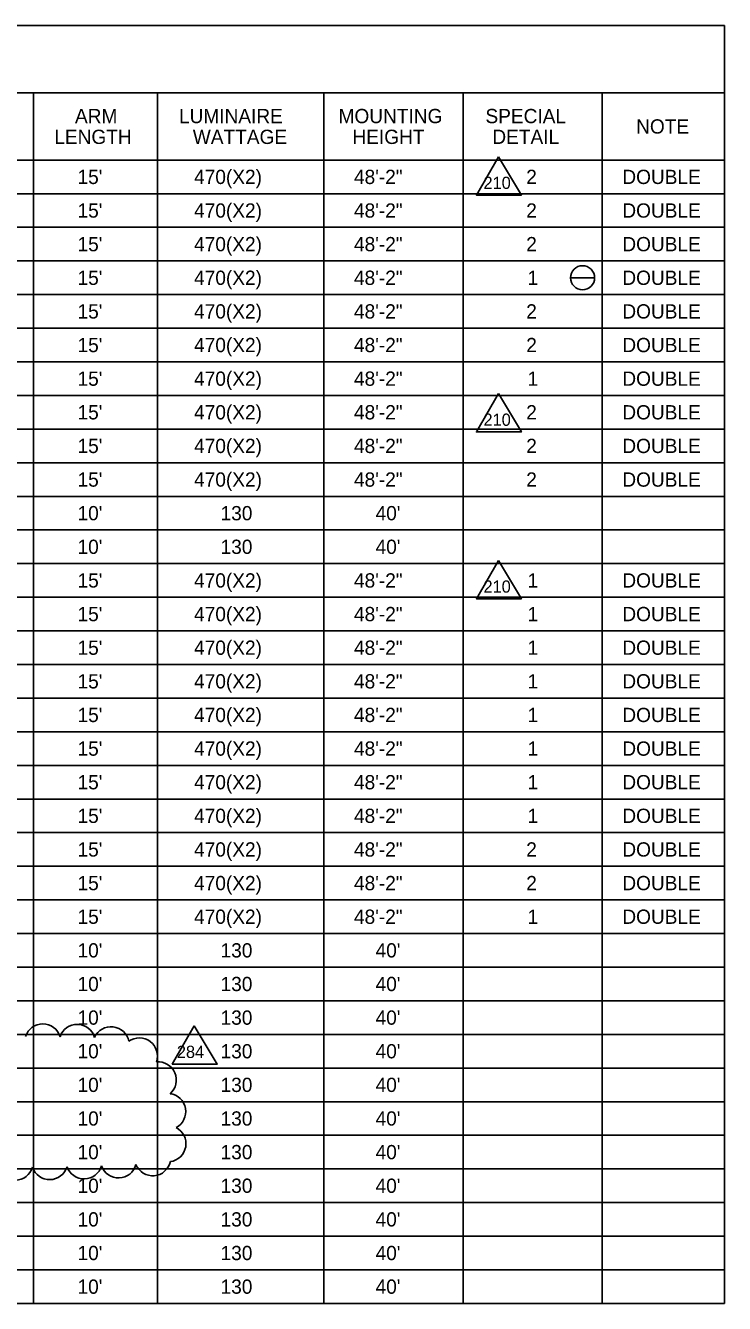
# Model space of a CAD drawing. Extents: x -816.7 to -800.7, y -2197.9 to -2187.9.
# Drawn here: x -812.04 to -808.61, y -2194.13 to -2187.86 of the extents above; entities that cross this region are included whole.
import ezdxf

# ---------------------------------------------------------------- set-up
doc = ezdxf.new("R2010")
doc.units = 0
for name, color, linetype in [('Cloud_dp', 7, 'Continuous'), ('SumBoxBorder_dp', 7, 'Continuous'), ('SumBoxLines_dp', 7, 'Continuous'), ('SumBoxLinesMin_dp', 7, 'Continuous'), ('TextLabel', 7, 'Continuous')]:
    doc.layers.add(name, color=color, linetype=linetype)

msp = doc.modelspace()

# ---------------------------------------------------------------- linework, layer by layer
at = {"layer": 'Cloud_dp'}
for points in [[(-809.7225, -2188.4998), (-809.8303, -2188.6879), (-809.6096, -2188.6879)], [(-809.7225, -2189.6621), (-809.8303, -2189.8502), (-809.6096, -2189.8502)], [(-809.7225, -2190.4807), (-809.8303, -2190.6688), (-809.6096, -2190.6688)], [(-811.215, -2192.7638), (-811.3227, -2192.9519), (-811.1021, -2192.9519)]]:
    msp.add_lwpolyline(points, close=True, dxfattribs=at)
for centre, radius, start, end in [((-811.9584, -2192.8432), 0.0887, 16.98047, 161.98047), ((-811.7894, -2192.8456), 0.0887, 16.37548, 161.37548), ((-811.6233, -2192.8569), 0.0887, 10.88611, 155.88611), ((-811.4843, -2192.9121), 0.0887, 340.74412, 125.74412), ((-811.3917, -2193.0297), 0.0887, 310.70221, 95.70221), ((-811.3452, -2193.185), 0.0887, 297.61139, 82.61139), ((-811.3444, -2193.3426), 0.0887, 277.92335, 62.92335), ((-811.4189, -2193.4112), 0.0888, 202.48791, 347.48791), ((-812.0936, -2193.4325), 0.0887, 198.24258, 343.24258), ((-811.9244, -2193.43), 0.0887, 198.48321, 343.48321), ((-811.7554, -2193.4265), 0.0887, 198.85675, 343.85675), ((-811.5865, -2193.4215), 0.0887, 199.56532, 344.56532)]:
    msp.add_arc(centre, radius, start, end, dxfattribs=at)
at = {"layer": 'SumBoxBorder_dp'}
for p, q in [((-816.0386, -2187.8562), (-808.6136, -2187.8562)), ((-808.6136, -2187.8562), (-808.6136, -2194.1262)), ((-808.6136, -2187.8562), (-808.6136, -2194.1262)), ((-816.0386, -2188.1862), (-808.6136, -2188.1862)), ((-816.0386, -2188.1862), (-808.6136, -2188.1862)), ((-816.0386, -2194.1262), (-808.6136, -2194.1262))]:
    msp.add_line(p, q, dxfattribs=at)
at = {"layer": 'SumBoxLines_dp'}
for p, q in [((-812.0036, -2188.1862), (-812.0036, -2194.1262)), ((-812.0036, -2188.1862), (-812.0036, -2194.1262)), ((-811.3961, -2188.1862), (-811.3961, -2194.1262)), ((-811.3961, -2188.1862), (-811.3961, -2194.1262)), ((-810.5786, -2188.1862), (-810.5786, -2194.1262)), ((-810.5786, -2188.1862), (-810.5786, -2194.1262)), ((-809.8961, -2188.1862), (-809.8961, -2194.1262)), ((-809.8961, -2188.1862), (-809.8961, -2192.3112)), ((-809.2136, -2188.1862), (-809.2136, -2194.1262)), ((-816.0386, -2188.5162), (-808.6136, -2188.5162)), ((-809.8961, -2192.4762), (-809.8961, -2194.1262))]:
    msp.add_line(p, q, dxfattribs=at)
at = {"layer": 'SumBoxLinesMin_dp'}
for p, q in [((-816.0386, -2188.5162), (-808.6136, -2188.5162)), ((-816.0386, -2188.6812), (-808.6136, -2188.6812)), ((-816.0386, -2188.6812), (-808.6136, -2188.6812)), ((-816.0386, -2188.8462), (-808.6136, -2188.8462)), ((-816.0386, -2188.8462), (-808.6136, -2188.8462)), ((-816.0386, -2189.0112), (-808.6136, -2189.0112)), ((-816.0386, -2189.0112), (-808.6136, -2189.0112)), ((-816.0386, -2189.1762), (-808.6136, -2189.1762)), ((-816.0386, -2189.1762), (-808.6136, -2189.1762)), ((-816.0386, -2189.3412), (-808.6136, -2189.3412)), ((-816.0386, -2189.3412), (-808.6136, -2189.3412)), ((-816.0386, -2189.5062), (-808.6136, -2189.5062)), ((-816.0386, -2189.5062), (-808.6136, -2189.5062)), ((-816.0386, -2189.6712), (-808.6136, -2189.6712)), ((-816.0386, -2189.6712), (-808.6136, -2189.6712)), ((-816.0386, -2189.8362), (-808.6136, -2189.8362)), ((-816.0386, -2189.8362), (-808.6136, -2189.8362)), ((-816.0386, -2190.0012), (-808.6136, -2190.0012)), ((-816.0386, -2190.0012), (-808.6136, -2190.0012)), ((-816.0386, -2190.1662), (-808.6136, -2190.1662)), ((-816.0386, -2190.1662), (-808.6136, -2190.1662)), ((-816.0386, -2190.3312), (-808.6136, -2190.3312)), ((-816.0386, -2190.3312), (-808.6136, -2190.3312)), ((-816.0386, -2190.4962), (-808.6136, -2190.4962)), ((-816.0386, -2190.4962), (-808.6136, -2190.4962)), ((-816.0386, -2190.6612), (-808.6136, -2190.6612)), ((-816.0386, -2190.6612), (-808.6136, -2190.6612)), ((-816.0386, -2190.8262), (-808.6136, -2190.8262)), ((-816.0386, -2190.8262), (-808.6136, -2190.8262)), ((-816.0386, -2190.9912), (-808.6136, -2190.9912)), ((-816.0386, -2190.9912), (-808.6136, -2190.9912)), ((-816.0386, -2191.1562), (-808.6136, -2191.1562)), ((-816.0386, -2191.1562), (-808.6136, -2191.1562)), ((-816.0386, -2191.3212), (-808.6136, -2191.3212)), ((-816.0386, -2191.3212), (-808.6136, -2191.3212)), ((-816.0386, -2191.4862), (-808.6136, -2191.4862)), ((-816.0386, -2191.4862), (-808.6136, -2191.4862)), ((-816.0386, -2191.6512), (-808.6136, -2191.6512)), ((-816.0386, -2191.6512), (-808.6136, -2191.6512)), ((-816.0386, -2191.8162), (-808.6136, -2191.8162)), ((-816.0386, -2191.8162), (-808.6136, -2191.8162)), ((-816.0386, -2191.9812), (-808.6136, -2191.9812)), ((-816.0386, -2191.9812), (-808.6136, -2191.9812)), ((-816.0386, -2192.1462), (-808.6136, -2192.1462)), ((-816.0386, -2192.1462), (-808.6136, -2192.1462)), ((-816.0386, -2192.3112), (-808.6136, -2192.3112)), ((-816.0386, -2192.3112), (-808.6136, -2192.3112)), ((-816.0386, -2192.4762), (-809.8961, -2192.4762)), ((-816.0386, -2192.4762), (-808.6136, -2192.4762)), ((-809.2136, -2192.4762), (-808.6136, -2192.4762)), ((-816.0386, -2192.6412), (-808.6136, -2192.6412)), ((-816.0386, -2192.6412), (-808.6136, -2192.6412)), ((-816.0386, -2192.8062), (-808.6136, -2192.8062)), ((-816.0386, -2192.8062), (-808.6136, -2192.8062)), ((-816.0386, -2192.9712), (-808.6136, -2192.9712)), ((-816.0386, -2192.9712), (-808.6136, -2192.9712)), ((-816.0386, -2193.1362), (-808.6136, -2193.1362)), ((-816.0386, -2193.1362), (-808.6136, -2193.1362)), ((-816.0386, -2193.3012), (-808.6136, -2193.3012)), ((-816.0386, -2193.3012), (-808.6136, -2193.3012)), ((-816.0386, -2193.4662), (-808.6136, -2193.4662)), ((-816.0386, -2193.4662), (-808.6136, -2193.4662)), ((-816.0386, -2193.6312), (-808.6136, -2193.6312)), ((-816.0386, -2193.6312), (-808.6136, -2193.6312)), ((-816.0386, -2193.7962), (-808.6136, -2193.7962)), ((-816.0386, -2193.7962), (-808.6136, -2193.7962)), ((-816.0386, -2193.9612), (-808.6136, -2193.9612)), ((-816.0386, -2193.9612), (-808.6136, -2193.9612))]:
    msp.add_line(p, q, dxfattribs=at)
at = {"layer": 'TextLabel'}
msp.add_line((-809.3691, -2189.0937), (-809.2505, -2189.0937), dxfattribs=at)
msp.add_line((-809.3691, -2189.0937), (-809.2505, -2189.0937), dxfattribs=at)
msp.add_circle((-809.3098, -2189.0937), 0.0593, dxfattribs=at)
msp.add_arc((-809.3098, -2189.0937), 0.0593, 0, 180, dxfattribs=at)

# ---------------------------------------------------------------- texts
at = {"layer": 'Cloud_dp'}
for s, p in [('210', (-809.7958, -2188.6578)), ('210', (-809.7958, -2189.8201)), ('210', (-809.7958, -2190.6387)), ('284', (-811.3004, -2192.9217))]:
    msp.add_text(s, height=0.05998, rotation=0, dxfattribs=at).set_placement(p)
at = {"layer": 'TextLabel'}
for s, p in [('ARM', (-811.8003, -2188.3352)), ('LUMINAIRE', (-811.29, -2188.3352)), ('MOUNTING', (-810.507, -2188.3352)), ('SPECIAL', (-809.7862, -2188.3352)), ('NOTE', (-809.0469, -2188.3862)), ('LENGTH', (-811.9018, -2188.4372)), ('WATTAGE', (-811.2222, -2188.4372)), ('HEIGHT', (-810.4388, -2188.4372)), ('DETAIL', (-809.7524, -2188.4372)), ("15'", (-811.7878, -2188.6337)), ('470(X2)', (-811.2158, -2188.6337)), ('48\'-2"', (-810.4313, -2188.6337)), ('2', (-809.5862, -2188.6337)), ('DOUBLE', (-809.1146, -2188.6337)), ("15'", (-811.7878, -2188.7987)), ('470(X2)', (-811.2158, -2188.7987)), ('48\'-2"', (-810.4313, -2188.7987)), ('2', (-809.5862, -2188.7987)), ('DOUBLE', (-809.1146, -2188.7987)), ("15'", (-811.7878, -2188.9637)), ('470(X2)', (-811.2158, -2188.9637)), ('48\'-2"', (-810.4313, -2188.9637)), ('2', (-809.5862, -2188.9637)), ('DOUBLE', (-809.1146, -2188.9637)), ("15'", (-811.7878, -2189.1287)), ('470(X2)', (-811.2158, -2189.1287)), ('48\'-2"', (-810.4313, -2189.1287)), ('1', (-809.5795, -2189.1287)), ('DOUBLE', (-809.1146, -2189.1287)), ("15'", (-811.7878, -2189.2937)), ('470(X2)', (-811.2158, -2189.2937)), ('48\'-2"', (-810.4313, -2189.2937)), ('2', (-809.5862, -2189.2937)), ('DOUBLE', (-809.1146, -2189.2937)), ("15'", (-811.7878, -2189.4587)), ('470(X2)', (-811.2158, -2189.4587)), ('48\'-2"', (-810.4313, -2189.4587)), ('2', (-809.5862, -2189.4587)), ('DOUBLE', (-809.1146, -2189.4587)), ("15'", (-811.7878, -2189.6237)), ('470(X2)', (-811.2158, -2189.6237)), ('48\'-2"', (-810.4313, -2189.6237)), ('1', (-809.5795, -2189.6237)), ('DOUBLE', (-809.1146, -2189.6237)), ("15'", (-811.7878, -2189.7887)), ('470(X2)', (-811.2158, -2189.7887)), ('48\'-2"', (-810.4313, -2189.7887)), ('2', (-809.5862, -2189.7887)), ('DOUBLE', (-809.1146, -2189.7887)), ("15'", (-811.7878, -2189.9537)), ('470(X2)', (-811.2158, -2189.9537)), ('48\'-2"', (-810.4313, -2189.9537)), ('2', (-809.5862, -2189.9537)), ('DOUBLE', (-809.1146, -2189.9537)), ('470(X2)', (-811.2158, -2190.1187)), ('48\'-2"', (-810.4313, -2190.1187)), ('2', (-809.5862, -2190.1187)), ('DOUBLE', (-809.1146, -2190.1187)), ("15'", (-811.7878, -2190.1187)), ("10'", (-811.7878, -2190.2837)), ('130', (-811.0859, -2190.2837)), ("40'", (-810.3253, -2190.2837)), ("10'", (-811.7878, -2190.4487)), ('130', (-811.0859, -2190.4487)), ("40'", (-810.3253, -2190.4487)), ("15'", (-811.7878, -2190.6137)), ('470(X2)', (-811.2158, -2190.6137)), ('48\'-2"', (-810.4313, -2190.6137)), ('1', (-809.5795, -2190.6137)), ('DOUBLE', (-809.1146, -2190.6137)), ("15'", (-811.7878, -2190.7787)), ('470(X2)', (-811.2158, -2190.7787)), ('48\'-2"', (-810.4313, -2190.7787)), ('1', (-809.5795, -2190.7787)), ('DOUBLE', (-809.1146, -2190.7787)), ("15'", (-811.7878, -2190.9437)), ('470(X2)', (-811.2158, -2190.9437)), ('48\'-2"', (-810.4313, -2190.9437)), ('1', (-809.5795, -2190.9437)), ('DOUBLE', (-809.1146, -2190.9437)), ("15'", (-811.7878, -2191.1087)), ('470(X2)', (-811.2158, -2191.1087)), ('48\'-2"', (-810.4313, -2191.1087)), ('1', (-809.5795, -2191.1087)), ('DOUBLE', (-809.1146, -2191.1087)), ("15'", (-811.7878, -2191.2737)), ('470(X2)', (-811.2158, -2191.2737)), ('48\'-2"', (-810.4313, -2191.2737)), ('1', (-809.5795, -2191.2737)), ('DOUBLE', (-809.1146, -2191.2737)), ('470(X2)', (-811.2158, -2191.4387)), ("15'", (-811.7878, -2191.4387)), ('48\'-2"', (-810.4313, -2191.4387)), ('1', (-809.5795, -2191.4387)), ('DOUBLE', (-809.1146, -2191.4387)), ("15'", (-811.7878, -2191.6037)), ('470(X2)', (-811.2158, -2191.6037)), ('48\'-2"', (-810.4313, -2191.6037)), ('1', (-809.5795, -2191.6037)), ('DOUBLE', (-809.1146, -2191.6037)), ("15'", (-811.7878, -2191.7687)), ('470(X2)', (-811.2158, -2191.7687)), ('48\'-2"', (-810.4313, -2191.7687)), ('1', (-809.5795, -2191.7687)), ('DOUBLE', (-809.1146, -2191.7687)), ("15'", (-811.7878, -2191.9337)), ('470(X2)', (-811.2158, -2191.9337)), ('48\'-2"', (-810.4313, -2191.9337)), ('2', (-809.5862, -2191.9337)), ('DOUBLE', (-809.1146, -2191.9337)), ("15'", (-811.7878, -2192.0987)), ('470(X2)', (-811.2158, -2192.0987)), ('48\'-2"', (-810.4313, -2192.0987)), ('2', (-809.5862, -2192.0987)), ('DOUBLE', (-809.1146, -2192.0987)), ("15'", (-811.7878, -2192.2637)), ('470(X2)', (-811.2158, -2192.2637)), ('48\'-2"', (-810.4313, -2192.2637)), ('1', (-809.5795, -2192.2637)), ('DOUBLE', (-809.1146, -2192.2637)), ("10'", (-811.7878, -2192.4287)), ('130', (-811.0859, -2192.4287)), ("40'", (-810.3253, -2192.4287)), ("10'", (-811.7878, -2192.5937)), ('130', (-811.0859, -2192.5937)), ("40'", (-810.3253, -2192.5937)), ("10'", (-811.7878, -2192.7587)), ('130', (-811.0859, -2192.7587)), ("40'", (-810.3253, -2192.7587)), ("10'", (-811.7878, -2192.9237)), ('130', (-811.0859, -2192.9237)), ("40'", (-810.3253, -2192.9237)), ("10'", (-811.7878, -2193.0887)), ('130', (-811.0859, -2193.0887)), ("40'", (-810.3253, -2193.0887)), ("10'", (-811.7878, -2193.2537)), ('130', (-811.0859, -2193.2537)), ("40'", (-810.3253, -2193.2537)), ("10'", (-811.7878, -2193.4187)), ('130', (-811.0859, -2193.4187)), ("40'", (-810.3253, -2193.4187)), ("10'", (-811.7878, -2193.5837)), ('130', (-811.0859, -2193.5837)), ("40'", (-810.3253, -2193.5837)), ("10'", (-811.7878, -2193.7487)), ('130', (-811.0859, -2193.7487)), ("40'", (-810.3253, -2193.7487)), ("10'", (-811.7878, -2193.9137)), ('130', (-811.0859, -2193.9137)), ("40'", (-810.3253, -2193.9137)), ("10'", (-811.7878, -2194.0787)), ('130', (-811.0859, -2194.0787)), ("40'", (-810.3253, -2194.0787))]:
    msp.add_text(s, height=0.07, dxfattribs=at).set_placement(p)

doc.saveas('drawing.dxf')
